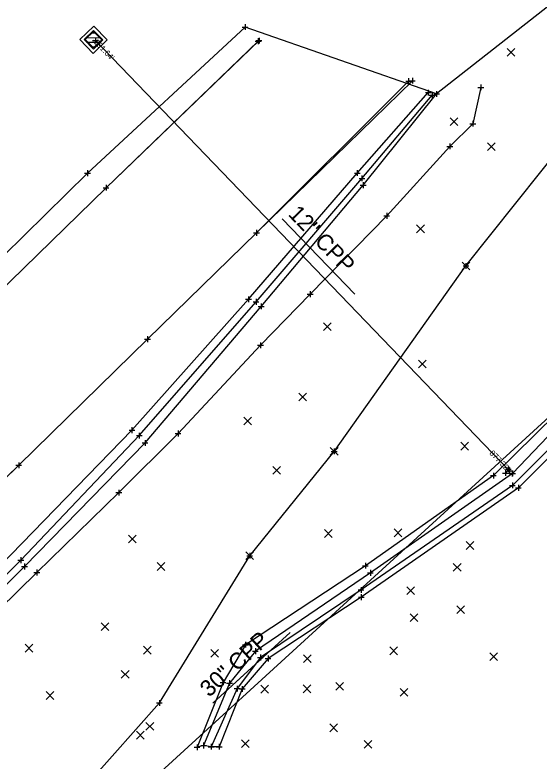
# Model space of a CAD drawing. Extents: x 236 to 155644, y 66 to 491728.
# Drawn here: x 148000 to 148090.1, y 487388.8 to 487517.2 of the extents above; entities that cross this region are included whole.
import ezdxf

# ---------------------------------------------------------------- set-up
doc = ezdxf.new("R2010")
doc.units = 0
for name, color, linetype in [('DR_X_Storm_Sewer', 7, 'Continuous'), ('DR_X_Text', 7, 'Continuous'), ('PM_X_Edge_Line', 7, 'Continuous'), ('PV_X_EOP', 7, 'Continuous'), ('PV_X_Shoulder', 7, 'Continuous'), ('PV_X_Shoulder_Aggregate', 7, 'Continuous'), ('RD_X_Cells', 7, 'Continuous'), ('RD_X_Concrete_Pad', 7, 'Continuous'), ('RD_X_GR_Rt', 7, 'Continuous'), ('RD_X_RR_Cells', 7, 'Continuous'), ('RW_X_Esmt_LA', 7, 'Continuous'), ('SC_Scratch1', 7, 'Continuous'), ('SV_P_Mon_Cells_Set', 7, 'Continuous'), ('SV_X_Mon_Cells_Found', 7, 'Continuous'), ('SV_X_Shot_Marker', 7, 'Continuous'), ('SV_X_Terrain_Boundary', 7, 'Continuous'), ('VG_X_Shrub_Line_Lt', 7, 'Continuous')]:
    doc.layers.add(name, color=color, linetype=linetype)

msp = doc.modelspace()

# ---------------------------------------------------------------- linework, layer by layer
at = {"layer": 'DR_X_Storm_Sewer'}
for p, q in [((148013.81, 487512.75), (148085.05, 487438.72)), ((147938.72, 487308.02), (148143.23, 487495.01))]:
    msp.add_line(p, q, dxfattribs=at)
at = {"layer": 'DR_X_Text'}
for p, q in [((148058.42, 487469.13), (148045.95, 487482.09)), ((148047.3, 487410.89), (148034.03, 487398.75)), ((148047.31, 487410.9), (148034.04, 487398.77))]:
    msp.add_line(p, q, dxfattribs=at)
at = {"layer": 'PM_X_Edge_Line'}
for points in [[(148041.8, 487512.67), (148015.64, 487487.44), (147982.57, 487455.18), (147948.86, 487422.36)], [(148068.33, 487505.86), (148041.51, 487479.67), (148022.76, 487461.37), (148000.61, 487439.67), (147970.2, 487410.16)]]:
    msp.add_lwpolyline(points, dxfattribs=at)
at = {"layer": 'PV_X_EOP'}
for points in [[(147693.25, 487187.07), (147735.46, 487223.2), (147776.17, 487259.34), (147831.17, 487309.51), (147863.85, 487340.33), (147885.66, 487361.04), (147949.12, 487422.42), (147982.57, 487455.18), (148015.64, 487487.44), (148041.95, 487512.76)], [(148067.69, 487505.78), (148041.51, 487479.67), (148022.76, 487461.37), (148000.61, 487439.67), (147970.81, 487410.54), (147942.69, 487383.21), (147911.46, 487353.05), (147868.4, 487312.17), (147833.06, 487279.09), (147795.98, 487245.09), (147757.86, 487210.93), (147709.11, 487169.11)]]:
    msp.add_lwpolyline(points, dxfattribs=at)
at = {"layer": 'PV_X_Shoulder'}
for points in [[(148039.55, 487515.09), (148012.45, 487489.95), (147979.89, 487457.95), (147954.94, 487433.78), (147944.06, 487423.78), (147944.07, 487423.66), (147935.56, 487423.33), (147926.85, 487427.94), (147923.37, 487432.95)], [(148040.01, 487254.43), (148031.73, 487276.29), (148021.08, 487296.53), (148006.49, 487319.06), (147989.88, 487340.16), (147972.51, 487362.29), (147968.79, 487370.23), (147967.39, 487384.39), (147970.87, 487395.55), (147976.24, 487401.99), (147999.31, 487424.29), (148020.09, 487445.71), (148040.14, 487468.23), (148058.86, 487489.97), (148071.06, 487503.8)]]:
    msp.add_lwpolyline(points, dxfattribs=at)
at = {"layer": 'PV_X_Shoulder_Aggregate'}
msp.add_lwpolyline([(148044.1, 487258.38), (148036.82, 487278.55), (148024.66, 487298.49), (148009.79, 487321.89), (147992.99, 487342.63), (147976.12, 487364.22), (147972.43, 487372.09), (147970.56, 487385.21), (147973.08, 487394.35), (147977.93, 487400.48), (148000.97, 487423.34), (148021.35, 487444.77), (148041.44, 487467.79), (148059.65, 487489.05), (148071.71, 487503.36)], dxfattribs=at)
at = {"layer": 'RD_X_Cells'}
for p, q in [((148039.05, 487515.09), (148040.05, 487515.09)), ((148039.55, 487515.59), (148039.55, 487514.59)), ((148039.55, 487515.09), (148039.55, 487515.09)), ((148041.3, 487512.67), (148042.3, 487512.67)), ((148041.45, 487512.76), (148042.45, 487512.76)), ((148041.8, 487513.17), (148041.8, 487512.17)), ((148041.8, 487512.67), (148041.8, 487512.67)), ((148041.95, 487513.26), (148041.95, 487512.26)), ((148041.95, 487512.76), (148041.95, 487512.76)), ((148067.69, 487506.28), (148067.69, 487505.28)), ((148068.33, 487506.36), (148068.33, 487505.36)), ((148067.19, 487505.78), (148068.19, 487505.78)), ((148067.69, 487505.78), (148067.69, 487505.78)), ((148067.83, 487505.86), (148068.83, 487505.86)), ((148068.33, 487505.86), (148068.33, 487505.86)), ((148080.11, 487505.2), (148080.11, 487504.2)), ((148070.56, 487503.8), (148071.56, 487503.8)), ((148071.06, 487504.3), (148071.06, 487503.3)), ((148071.06, 487503.8), (148071.06, 487503.8)), ((148071.71, 487503.86), (148071.71, 487502.86)), ((148072, 487503.57), (148073, 487503.57)), ((148072.5, 487504.07), (148072.5, 487503.07)), ((148072.5, 487503.57), (148072.5, 487503.57)), ((148079.61, 487504.7), (148080.61, 487504.7)), ((148080.11, 487504.7), (148080.11, 487504.7)), ((148071.21, 487503.36), (148072.21, 487503.36)), ((148071.71, 487503.36), (148071.71, 487503.36)), ((148078.23, 487498.45), (148079.23, 487498.45)), ((148078.73, 487498.95), (148078.73, 487497.95)), ((148078.73, 487498.45), (148078.73, 487498.45)), ((148074.28, 487494.55), (148075.28, 487494.55)), ((148074.78, 487495.05), (148074.78, 487494.05)), ((148074.78, 487494.55), (148074.78, 487494.55)), ((148011.95, 487489.95), (148012.95, 487489.95)), ((148012.45, 487490.45), (148012.45, 487489.45)), ((148012.45, 487489.95), (148012.45, 487489.95)), ((148058.36, 487489.97), (148059.36, 487489.97)), ((148058.86, 487490.47), (148058.86, 487489.47)), ((148058.86, 487489.97), (148058.86, 487489.97)), ((148059.65, 487489.55), (148059.65, 487488.55)), ((148059.15, 487489.05), (148060.15, 487489.05)), ((148059.65, 487489.05), (148059.65, 487489.05)), ((148059.87, 487488.37), (148059.87, 487487.37)), ((148015.14, 487487.44), (148016.14, 487487.44)), ((148015.14, 487487.44), (148016.14, 487487.44)), ((148015.64, 487487.94), (148015.64, 487486.94)), ((148015.64, 487487.94), (148015.64, 487486.94)), ((148015.64, 487487.44), (148015.64, 487487.44)), ((148015.64, 487487.44), (148015.64, 487487.44)), ((148059.37, 487487.87), (148060.37, 487487.87)), ((148059.87, 487487.87), (148059.87, 487487.87)), ((148063.91, 487483.11), (148063.91, 487482.11)), ((148063.41, 487482.61), (148064.41, 487482.61)), ((148063.91, 487482.61), (148063.91, 487482.61)), ((148041.01, 487479.67), (148042.01, 487479.67)), ((148041.01, 487479.67), (148042.01, 487479.67)), ((148041.51, 487480.17), (148041.51, 487479.17)), ((148041.51, 487480.17), (148041.51, 487479.17)), ((148041.51, 487479.67), (148041.51, 487479.67)), ((148041.51, 487479.67), (148041.51, 487479.67)), ((148077.04, 487473.98), (148078.04, 487473.98)), ((148077.54, 487474.48), (148077.54, 487473.48)), ((148077.54, 487473.98), (148077.54, 487473.98)), ((148050.25, 487469.13), (148051.25, 487469.13)), ((148050.75, 487469.63), (148050.75, 487468.63)), ((148050.75, 487469.13), (148050.75, 487469.13)), ((148039.64, 487468.23), (148040.64, 487468.23)), ((148040.14, 487468.73), (148040.14, 487467.73)), ((148040.14, 487468.23), (148040.14, 487468.23)), ((148040.94, 487467.79), (148041.94, 487467.79)), ((148041.44, 487468.29), (148041.44, 487467.29)), ((148041.44, 487467.79), (148041.44, 487467.79)), ((148041.83, 487467.01), (148042.83, 487467.01)), ((148042.33, 487467.51), (148042.33, 487466.51)), ((148042.33, 487467.01), (148042.33, 487467.01)), ((148022.26, 487461.37), (148023.26, 487461.37)), ((148022.26, 487461.37), (148023.26, 487461.37)), ((148022.76, 487461.87), (148022.76, 487460.87)), ((148022.76, 487461.87), (148022.76, 487460.87)), ((148022.76, 487461.37), (148022.76, 487461.37)), ((148022.76, 487461.37), (148022.76, 487461.37)), ((148041.71, 487460.32), (148042.71, 487460.32)), ((148042.21, 487460.82), (148042.21, 487459.82)), ((148042.21, 487460.32), (148042.21, 487460.32)), ((148019.59, 487445.71), (148020.59, 487445.71)), ((148020.09, 487446.21), (148020.09, 487445.21)), ((148020.09, 487445.71), (148020.09, 487445.71)), ((148020.85, 487444.77), (148021.85, 487444.77)), ((148021.35, 487445.27), (148021.35, 487444.27)), ((148021.35, 487444.77), (148021.35, 487444.77)), ((148027.52, 487445.14), (148028.52, 487445.14)), ((148028.02, 487445.64), (148028.02, 487444.64)), ((148028.02, 487445.14), (148028.02, 487445.14)), ((148021.84, 487443.51), (148022.84, 487443.51)), ((148022.34, 487444.01), (148022.34, 487443.01)), ((148022.34, 487443.51), (148022.34, 487443.51)), ((148054.38, 487442.07), (148055.38, 487442.07)), ((148054.88, 487442.57), (148054.88, 487441.57)), ((148054.88, 487442.07), (148054.88, 487442.07)), ((148000.11, 487439.67), (148001.11, 487439.67)), ((148000.11, 487439.67), (148001.11, 487439.67)), ((148000.61, 487440.17), (148000.61, 487439.17)), ((148000.61, 487440.17), (148000.61, 487439.17)), ((148000.61, 487439.67), (148000.61, 487439.67)), ((148000.61, 487439.67), (148000.61, 487439.67)), ((148084.84, 487439.48), (148084.84, 487438.48)), ((148082.27, 487438.39), (148082.27, 487437.39)), ((148083.85, 487438.34), (148084.85, 487438.34)), ((148084.34, 487438.98), (148085.34, 487438.98)), ((148084.35, 487438.84), (148084.35, 487437.84)), ((148084.35, 487438.34), (148084.35, 487438.34)), ((148084.84, 487438.98), (148084.84, 487438.98)), ((148084.98, 487438.24), (148085.98, 487438.24)), ((148085.07, 487438.28), (148086.07, 487438.28)), ((148085.48, 487438.74), (148085.48, 487437.74)), ((148085.48, 487438.24), (148085.48, 487438.24)), ((148085.57, 487438.78), (148085.57, 487437.78)), ((148085.57, 487438.28), (148085.57, 487438.28)), ((148081.77, 487437.89), (148082.77, 487437.89)), ((148082.27, 487437.89), (148082.27, 487437.89)), ((148085.53, 487436.71), (148085.53, 487435.71)), ((148017.84, 487435.47), (148017.84, 487434.47)), ((148085.03, 487436.21), (148086.03, 487436.21)), ((148085.53, 487436.21), (148085.53, 487436.21)), ((148086.06, 487435.8), (148087.06, 487435.8)), ((148086.56, 487436.3), (148086.56, 487435.3)), ((148086.56, 487435.8), (148086.56, 487435.8)), ((148017.34, 487434.97), (148018.34, 487434.97)), ((148017.84, 487434.97), (148017.84, 487434.97)), ((148039.85, 487424.1), (148040.85, 487424.1)), ((148040.35, 487424.6), (148040.35, 487423.6)), ((148040.35, 487424.1), (148040.35, 487424.1)), ((148000.47, 487423.34), (148001.47, 487423.34)), ((148000.97, 487423.84), (148000.97, 487422.84)), ((148000.97, 487423.34), (148000.97, 487423.34)), ((148001.62, 487422.75), (148001.62, 487421.75)), ((148060.24, 487422.88), (148060.24, 487421.88)), ((148001.12, 487422.25), (148002.12, 487422.25)), ((148001.62, 487422.25), (148001.62, 487422.25)), ((148003.73, 487421.73), (148003.73, 487420.73)), ((148059.74, 487422.38), (148060.74, 487422.38)), ((148060.24, 487422.38), (148060.24, 487422.38)), ((148061.1, 487421.65), (148061.1, 487420.65)), ((148003.23, 487421.23), (148004.23, 487421.23)), ((148003.73, 487421.23), (148003.73, 487421.23)), ((148060.6, 487421.15), (148061.6, 487421.15)), ((148061.1, 487421.15), (148061.1, 487421.15)), ((148059.5, 487418.72), (148059.5, 487417.72)), ((148059, 487418.22), (148060, 487418.22)), ((148059.5, 487418.22), (148059.5, 487418.22)), ((148059.54, 487417.47), (148059.54, 487416.47)), ((148059.04, 487416.97), (148060.04, 487416.97)), ((148059.54, 487416.97), (148059.54, 487416.97)), ((148039.12, 487408.79), (148040.12, 487408.79)), ((148039.62, 487409.29), (148039.62, 487408.29)), ((148039.62, 487408.79), (148039.62, 487408.79)), ((148040.83, 487407.69), (148041.83, 487407.69)), ((148041.33, 487408.19), (148041.33, 487407.19)), ((148041.33, 487407.69), (148041.33, 487407.69)), ((148041.68, 487406.6), (148042.68, 487406.6)), ((148042.18, 487407.1), (148042.18, 487406.1)), ((148042.18, 487406.6), (148042.18, 487406.6)), ((148043, 487406.42), (148044, 487406.42)), ((148043.5, 487406.92), (148043.5, 487405.92)), ((148043.5, 487406.42), (148043.5, 487406.42)), ((148035.26, 487402.31), (148036.26, 487402.31)), ((148035.76, 487402.81), (148035.76, 487401.81)), ((148035.76, 487402.31), (148035.76, 487402.31)), ((148036.36, 487402.19), (148037.36, 487402.19)), ((148036.86, 487402.69), (148036.86, 487401.69)), ((148036.86, 487402.19), (148036.86, 487402.19)), ((148037.68, 487401.24), (148038.68, 487401.24)), ((148038.18, 487401.74), (148038.18, 487400.74)), ((148038.18, 487401.24), (148038.18, 487401.24)), ((148038.57, 487401.17), (148039.57, 487401.17)), ((148039.07, 487401.67), (148039.07, 487400.67)), ((148039.07, 487401.17), (148039.07, 487401.17)), ((148024.31, 487398.77), (148025.31, 487398.77)), ((148024.81, 487399.27), (148024.81, 487398.27)), ((148024.81, 487398.77), (148024.81, 487398.77)), ((148032.42, 487391.94), (148032.42, 487390.94)), ((148030.79, 487391.14), (148031.79, 487391.14)), ((148031.29, 487391.64), (148031.29, 487390.64)), ((148031.29, 487391.14), (148031.29, 487391.14)), ((148031.92, 487391.44), (148032.92, 487391.44)), ((148032.42, 487391.44), (148032.42, 487391.44)), ((148033.23, 487391.23), (148034.23, 487391.23)), ((148033.73, 487391.73), (148033.73, 487390.73)), ((148033.73, 487391.23), (148033.73, 487391.23)), ((148034.59, 487391.23), (148035.59, 487391.23)), ((148035.09, 487391.73), (148035.09, 487390.73)), ((148035.09, 487391.23), (148035.09, 487391.23))]:
    msp.add_line(p, q, dxfattribs=at)
at = {"layer": 'RD_X_Concrete_Pad'}
for p, q in [((148032.42, 487391.44), (148031.29, 487391.14)), ((148033.73, 487391.23), (148032.42, 487391.44)), ((148035.09, 487391.23), (148033.73, 487391.23))]:
    msp.add_line(p, q, dxfattribs=at)
for points in [[(148135.1, 487489.43), (148118.21, 487473.29), (148082.27, 487437.89), (148060.24, 487422.38), (148039.62, 487408.79), (148035.76, 487402.31), (148031.29, 487391.14)], [(148137.63, 487486.78), (148121.32, 487470.63), (148086.56, 487435.8), (148059.54, 487416.97), (148043.5, 487406.42), (148039.07, 487401.17), (148035.09, 487391.23)]]:
    msp.add_lwpolyline(points, dxfattribs=at)
at = {"layer": 'RD_X_GR_Rt'}
msp.add_lwpolyline([(148049.95, 487260.21), (148039.14, 487279.06), (148026.35, 487299.91), (148011.07, 487322.72), (147994.43, 487343.79), (147978.48, 487365.11), (147974.04, 487373.33), (147972.54, 487385), (147974.46, 487393.64), (147978.72, 487399.62), (148001.62, 487422.25), (148022.34, 487443.51), (148042.33, 487467.01), (148059.87, 487487.87), (148072.5, 487503.57)], dxfattribs=at)
at = {"layer": 'RD_X_RR_Cells'}
for p, q in [((148013.31, 487512.75), (148014.31, 487512.75)), ((148013.81, 487513.25), (148013.81, 487512.25)), ((148013.81, 487512.75), (148013.81, 487512.75)), ((148084.55, 487438.72), (148085.55, 487438.72)), ((148085.05, 487439.22), (148085.05, 487438.22)), ((148085.05, 487438.72), (148085.05, 487438.72))]:
    msp.add_line(p, q, dxfattribs=at)
at = {"layer": 'RW_X_Esmt_LA'}
for points in [[(148080.11, 487504.7), (148078.73, 487498.45), (148074.78, 487494.55), (148063.91, 487482.61), (148050.75, 487469.13), (148042.21, 487460.32), (148028.02, 487445.14), (148017.84, 487434.97), (148003.73, 487421.23), (147990.69, 487408.5), (147981.21, 487398.33), (147977.27, 487390.32), (147975.76, 487382.92), (147979.63, 487369.33), (147989.69, 487356.53), (148002.86, 487339.81), (148015.14, 487324.04), (148026.82, 487306.31), (148037.3, 487291.21), (148044.4, 487279.13), (148050.68, 487271.17)], [(148135.1, 487489.43), (148118.21, 487473.29), (148082.27, 487437.89), (148060.24, 487422.38), (148039.62, 487408.79), (148035.76, 487402.31), (148031.29, 487391.14)], [(148135.68, 487488.78), (148118.2, 487472.47), (148085.57, 487438.28), (148061.1, 487421.15), (148041.33, 487407.69), (148036.86, 487402.19), (148032.42, 487391.44)], [(148137.16, 487487.36), (148120.78, 487471.35), (148085.53, 487436.21), (148059.5, 487418.22), (148042.18, 487406.6), (148038.18, 487401.24), (148033.73, 487391.23)], [(148084.84, 487438.98), (148084.35, 487438.34), (148085.48, 487438.24)]]:
    msp.add_lwpolyline(points, dxfattribs=at)
at = {"layer": 'SV_P_Mon_Cells_Set'}
for p, q in [((148084.65, 487510.05), (148085.98, 487511.38)), ((148084.65, 487511.38), (148085.98, 487510.05)), ((148074.81, 487498.14), (148076.14, 487499.47)), ((148074.81, 487499.47), (148076.14, 487498.14)), ((148081.25, 487493.82), (148082.58, 487495.16)), ((148081.25, 487495.16), (148082.58, 487493.82)), ((148069.06, 487479.7), (148070.39, 487481.03)), ((148069.06, 487481.03), (148070.39, 487479.7)), ((148076.88, 487473.31), (148078.21, 487474.65)), ((148076.88, 487474.65), (148078.21, 487473.31)), ((148053.03, 487462.85), (148054.37, 487464.19)), ((148053.03, 487464.19), (148054.37, 487462.85)), ((148069.39, 487456.44), (148070.72, 487457.78)), ((148069.39, 487457.78), (148070.72, 487456.44)), ((148048.77, 487450.74), (148050.11, 487452.07)), ((148048.77, 487452.07), (148050.11, 487450.74)), ((148039.35, 487446.64), (148040.68, 487447.97)), ((148039.35, 487447.97), (148040.68, 487446.64)), ((148076.64, 487442.28), (148077.98, 487443.62)), ((148076.64, 487443.62), (148077.98, 487442.28)), ((148054.21, 487441.41), (148055.54, 487442.74)), ((148054.21, 487442.74), (148055.54, 487441.41)), ((148044.31, 487438.12), (148045.65, 487439.45)), ((148044.31, 487439.45), (148045.65, 487438.12)), ((148053.22, 487427.27), (148054.55, 487428.6)), ((148053.22, 487428.6), (148054.55, 487427.27)), ((148065.2, 487427.37), (148066.53, 487428.71)), ((148065.2, 487428.71), (148066.53, 487427.37)), ((148019.5, 487426.31), (148020.83, 487427.65)), ((148019.5, 487427.65), (148020.83, 487426.31)), ((148077.58, 487425.19), (148078.91, 487426.53)), ((148077.58, 487426.53), (148078.91, 487425.19)), ((148039.69, 487423.43), (148041.02, 487424.77)), ((148039.69, 487424.77), (148041.02, 487423.43)), ((148024.44, 487421.59), (148025.77, 487422.93)), ((148024.44, 487422.93), (148025.77, 487421.59)), ((148075.37, 487421.45), (148076.71, 487422.78)), ((148075.37, 487422.78), (148076.71, 487421.45)), ((148067.36, 487417.41), (148068.69, 487418.74)), ((148067.36, 487418.74), (148068.69, 487417.41)), ((148075.95, 487414.16), (148077.28, 487415.5)), ((148075.95, 487415.5), (148077.28, 487414.16)), ((148067.96, 487412.77), (148069.29, 487414.1)), ((148067.96, 487414.1), (148069.29, 487412.77)), ((148014.79, 487411.24), (148016.12, 487412.58)), ((148014.79, 487412.58), (148016.12, 487411.24)), ((148001.73, 487407.53), (148003.06, 487408.86)), ((148001.73, 487408.86), (148003.06, 487407.53)), ((148022.06, 487407.19), (148023.39, 487408.52)), ((148022.06, 487408.52), (148023.39, 487407.19)), ((148033.64, 487406.65), (148034.97, 487407.98)), ((148033.64, 487407.98), (148034.97, 487406.65)), ((148064.44, 487407.06), (148065.77, 487408.4)), ((148064.44, 487408.4), (148065.77, 487407.06)), ((148081.64, 487406.07), (148082.97, 487407.41)), ((148081.64, 487407.41), (148082.97, 487406.07)), ((148049.58, 487405.73), (148050.91, 487407.06)), ((148049.58, 487407.06), (148050.91, 487405.73)), ((148018.26, 487403.02), (148019.59, 487404.35)), ((148018.26, 487404.35), (148019.59, 487403.02)), ((148055.15, 487400.98), (148056.48, 487402.31)), ((148055.15, 487402.31), (148056.48, 487400.98)), ((148042.24, 487400.48), (148043.58, 487401.82)), ((148042.24, 487401.82), (148043.58, 487400.48)), ((148049.54, 487400.53), (148050.88, 487401.86)), ((148049.54, 487401.86), (148050.88, 487400.53)), ((148066.22, 487399.94), (148067.55, 487401.27)), ((148066.22, 487401.27), (148067.55, 487399.94)), ((148005.34, 487399.39), (148006.67, 487400.73)), ((148005.34, 487400.73), (148006.67, 487399.39)), ((148022.5, 487394.09), (148023.84, 487395.42)), ((148022.5, 487395.42), (148023.84, 487394.09)), ((148054.13, 487393.81), (148055.47, 487395.15)), ((148054.13, 487395.15), (148055.47, 487393.81)), ((148020.88, 487392.56), (148022.21, 487393.9)), ((148020.88, 487393.9), (148022.21, 487392.56)), ((148038.94, 487391.12), (148040.27, 487392.45)), ((148038.94, 487392.45), (148040.27, 487391.12)), ((148060.03, 487390.99), (148061.36, 487392.32)), ((148060.03, 487392.32), (148061.36, 487390.99))]:
    msp.add_line(p, q, dxfattribs=at)
at = {"layer": 'SV_X_Mon_Cells_Found'}
for p, q in [((148013.06, 487514.09), (148013.94, 487514.07)), ((148012.25, 487513.3), (148014.73, 487513.26)), ((148012.28, 487512.5), (148014.68, 487512.47)), ((148013.07, 487511.69), (148013.87, 487511.68))]:
    msp.add_line(p, q, dxfattribs=at)
for points in [[(148013.51, 487515.26), (148015.84, 487512.87), (148013.45, 487510.55), (148011.13, 487512.93)], [(148013.5, 487514.52), (148015.1, 487512.88), (148013.46, 487511.28), (148011.86, 487512.92)], [(148013.5, 487514.32), (148014.9, 487512.89), (148013.47, 487511.49), (148012.07, 487512.92)]]:
    msp.add_lwpolyline(points, close=True, dxfattribs=at)
at = {"layer": 'SV_X_Shot_Marker'}
for p, q in [((148014.68, 487514.07), (148014.68, 487514.07)), ((148012.79, 487513.62), (148012.79, 487513.62)), ((148013.48, 487512.9), (148013.48, 487512.9)), ((148013.48, 487512.9), (148013.48, 487512.9)), ((148013.48, 487512.9), (148013.48, 487512.9)), ((148014.2, 487513.6), (148014.2, 487513.6)), ((148012.29, 487511.74), (148012.29, 487511.74)), ((148012.77, 487512.21), (148012.77, 487512.21)), ((148014.18, 487512.19), (148014.18, 487512.19))]:
    msp.add_line(p, q, dxfattribs=at)
at = {"layer": 'SV_X_Terrain_Boundary'}
msp.add_lwpolyline([(147858, 487228.49), (147956.68, 487242.9), (147993.48, 487240.75), (148012.53, 487250.31), (148040.01, 487254.43), (148050.68, 487271.17), (148065.88, 487315.67), (148068.21, 487324.16), (148070.96, 487348.22), (148109.64, 487419.64), (148166.53, 487492.32), (148219.31, 487546.27), (148225.48, 487568.96), (148188.76, 487579.34), (148179.33, 487583.76), (148163.97, 487583.53), (148146.57, 487569.78), (148137.14, 487554.39), (148072.5, 487503.57), (148039.55, 487515.09), (148012.45, 487489.95), (147979.89, 487457.95), (147923.37, 487432.95), (147880.57, 487395.98)], dxfattribs=at)
at = {"layer": 'VG_X_Shrub_Line_Lt'}
msp.add_lwpolyline([(148042.73, 487318.39), (148018.94, 487349.2), (148000.42, 487371.25), (148024.81, 487398.77), (148040.35, 487424.1), (148054.88, 487442.07), (148077.54, 487473.98), (148094.74, 487495.57), (148106.71, 487512.79), (148103.29, 487524.93)], dxfattribs=at)

# ---------------------------------------------------------------- texts
at = {"layer": 'DR_X_Text'}
for s, rotation, p in [('12" CPP', 313.9009, (148046.82, 487482.77)), ('30" CPP', 42.439, (148033.38, 487399.66)), ('30" CPP', 42.4365, (148033.37, 487399.64))]:
    msp.add_text(s, height=2.8, rotation=rotation, dxfattribs=at).set_placement(p)
at = {"layer": 'SC_Scratch1'}
for s, p in [("891.64'", (148013.45, 487512.4)), ("877.32'", (148081.5, 487441.68))]:
    msp.add_text(s, height=1, rotation=313.9009, dxfattribs=at).set_placement(p)

doc.saveas('drawing.dxf')
